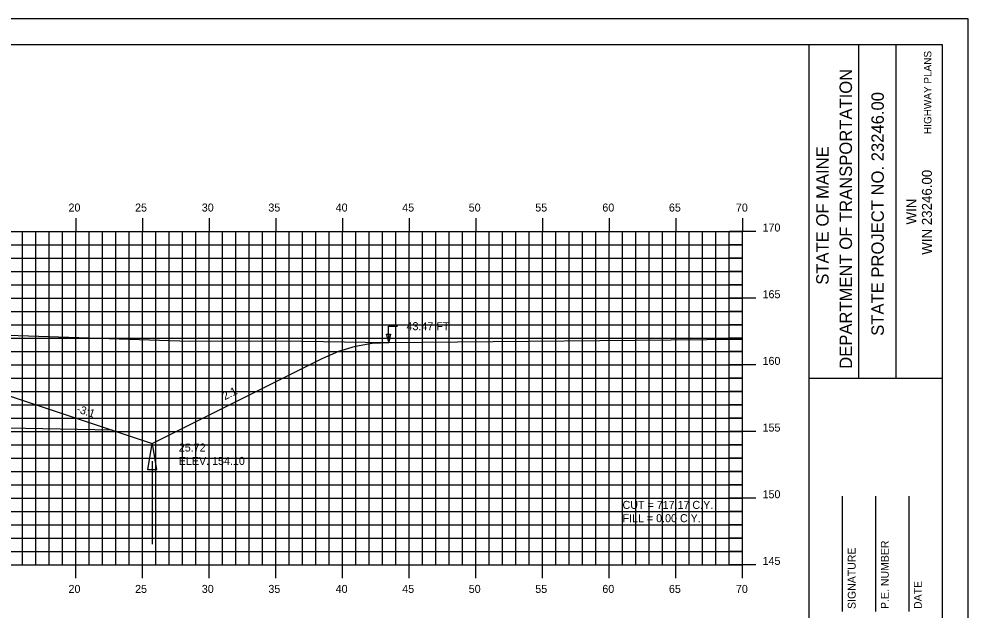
# Model space of a CAD drawing. Extents: x 1143198 to 1143368, y 608981 to 609091.
# Drawn here: x 1143297.1 to 1143368.2, y 609047 to 609091.3 of the extents above; entities that cross this region are included whole.
import ezdxf

# ---------------------------------------------------------------- set-up
doc = ezdxf.new("R2010")
doc.units = 0
for name, color, linetype in [('ANNOTATION', 7, 'Continuous'), ('BORDER', 7, 'Continuous'), ('D_Drainage_Ditch_Line', 7, 'Continuous'), ('D_Roadway_SlopeLines', 7, 'Continuous'), ('D_Roadway_SubGrade', 7, 'Continuous'), ('D_Text_Standard', 7, 'Continuous'), ('H_V ANNOTATION', 7, 'Continuous'), ('HIGHWAY_TITLE', 7, 'Continuous'), ('MAJOR', 7, 'Continuous'), ('MINOR', 7, 'Continuous'), ('PLOT BOUNDARY', 7, 'Continuous'), ('S_Roadway_Centerline', 7, 'Continuous')]:
    doc.layers.add(name, color=color, linetype=linetype)

msp = doc.modelspace()

# ---------------------------------------------------------------- linework, layer by layer
msp.add_lwpolyline([(1143238.561, 609066.856), (1143239.811, 609066.712), (1143241.061, 609066.431), (1143242.311, 609066.013), (1143243.561, 609065.457), (1143255.598, 609059.438), (1143258.598, 609060.438), (1143266.322, 609063.012), (1143266.323, 609063.012), (1143270.323, 609063.172), (1143281.323, 609063.392), (1143292.323, 609063.172), (1143296.323, 609063.012), (1143304.047, 609060.438), (1143307.047, 609059.438), (1143319.789, 609065.809), (1143321.039, 609066.354), (1143322.289, 609066.738), (1143323.539, 609066.962), (1143324.789, 609067.025)])
at = {"layer": 'BORDER'}
for p, q in [((1143356.323, 608984.335), (1143356.323, 609089.335)), ((1143360.052, 609064.332), (1143360.052, 609089.332)), ((1143362.847, 609064.332), (1143362.847, 609089.332)), ((1143356.324, 609064.329), (1143366.323, 609064.329)), ((1143358.823, 609046.838), (1143358.823, 609055.485)), ((1143361.323, 609046.838), (1143361.323, 609055.485)), ((1143363.823, 609046.838), (1143363.823, 609055.485))]:
    msp.add_line(p, q, dxfattribs=at)
msp.add_lwpolyline([(1143206.323, 608984.335), (1143366.323, 608984.335), (1143366.323, 609089.335), (1143206.323, 609089.335)], close=True, dxfattribs=at)
at = {"layer": 'D_Drainage_Ditch_Line'}
msp.add_line((1143307.047, 609058.126), (1143307.046, 609051.882), dxfattribs=at)
msp.add_lwpolyline([(1143307.375, 609057.469), (1143306.718, 609057.469), (1143307.047, 609059.438)], close=True, dxfattribs=at)
at = {"layer": 'D_Roadway_SlopeLines'}
for points in [[(1143307.047, 609059.438), (1143319.789, 609065.809), (1143321.039, 609066.354), (1143322.289, 609066.738), (1143323.539, 609066.962), (1143324.789, 609067.025)], [(1143304.047, 609060.438), (1143307.047, 609059.438)]]:
    msp.add_lwpolyline(points, dxfattribs=at)
at = {"layer": 'D_Roadway_SubGrade'}
msp.add_lwpolyline([(1143292.323, 609062.756), (1143292.323, 609062.922), (1143296.323, 609062.762), (1143296.323, 609063.012), (1143296.323, 609063.012), (1143304.047, 609060.438), (1143292.323, 609060.672)], close=True, dxfattribs=at)
at = {"layer": 'D_Text_Standard'}
msp.add_lwpolyline([(1143324.789, 609067.059), (1143324.632, 609067.638), (1143324.923, 609067.644)], close=True, dxfattribs=at)
msp.add_lwpolyline([(1143324.789, 609067.059), (1143324.765, 609068.237), (1143325.445, 609068.237)], dxfattribs=at)
at = {"layer": 'MAJOR'}
for p, q in [((1143301.323, 609076.337), (1143301.323, 609075.335)), ((1143306.323, 609076.337), (1143306.323, 609075.335)), ((1143311.323, 609076.337), (1143311.323, 609075.335)), ((1143316.323, 609076.337), (1143316.323, 609075.335)), ((1143321.323, 609076.337), (1143321.323, 609075.335)), ((1143326.323, 609076.337), (1143326.323, 609075.335)), ((1143331.323, 609076.337), (1143331.323, 609075.335)), ((1143336.323, 609076.337), (1143336.323, 609075.335)), ((1143341.323, 609076.337), (1143341.323, 609075.335)), ((1143346.323, 609076.337), (1143346.323, 609075.335)), ((1143351.323, 609076.337), (1143351.323, 609075.335)), ((1143211.323, 609075.335), (1143351.323, 609075.335)), ((1143211.323, 609075.335), (1143351.323, 609075.335)), ((1143301.323, 609050.335), (1143301.323, 609075.335)), ((1143306.323, 609050.335), (1143306.323, 609075.335)), ((1143311.323, 609050.335), (1143311.323, 609075.335)), ((1143316.323, 609050.335), (1143316.323, 609075.335)), ((1143321.323, 609050.335), (1143321.323, 609075.335)), ((1143326.323, 609050.335), (1143326.323, 609075.335)), ((1143331.323, 609050.335), (1143331.323, 609075.335)), ((1143336.323, 609050.335), (1143336.323, 609075.335)), ((1143341.323, 609050.335), (1143341.323, 609075.335)), ((1143346.323, 609050.335), (1143346.323, 609075.335)), ((1143352.325, 609075.335), (1143350.321, 609075.335)), ((1143351.323, 609050.335), (1143351.323, 609075.335)), ((1143351.323, 609050.335), (1143351.323, 609075.335)), ((1143211.323, 609070.335), (1143351.323, 609070.335)), ((1143352.325, 609070.335), (1143350.321, 609070.335)), ((1143211.323, 609065.335), (1143351.323, 609065.335)), ((1143352.325, 609065.335), (1143350.321, 609065.335)), ((1143211.323, 609060.335), (1143351.323, 609060.335)), ((1143352.325, 609060.335), (1143350.321, 609060.335)), ((1143211.323, 609055.335), (1143351.323, 609055.335)), ((1143352.325, 609055.335), (1143350.321, 609055.335)), ((1143211.323, 609050.335), (1143351.323, 609050.335)), ((1143211.323, 609050.335), (1143351.323, 609050.335)), ((1143301.323, 609049.333), (1143301.323, 609050.335)), ((1143306.323, 609049.333), (1143306.323, 609050.335)), ((1143311.323, 609049.333), (1143311.323, 609050.335)), ((1143316.323, 609049.333), (1143316.323, 609050.335)), ((1143321.323, 609049.333), (1143321.323, 609050.335)), ((1143326.323, 609049.333), (1143326.323, 609050.335)), ((1143331.323, 609049.333), (1143331.323, 609050.335)), ((1143336.323, 609049.333), (1143336.323, 609050.335)), ((1143341.323, 609049.333), (1143341.323, 609050.335)), ((1143346.323, 609049.333), (1143346.323, 609050.335)), ((1143352.325, 609050.335), (1143350.321, 609050.335)), ((1143351.323, 609049.333), (1143351.323, 609050.335))]:
    msp.add_line(p, q, dxfattribs=at)
at = {"layer": 'MINOR'}
for p, q in [((1143297.323, 609050.335), (1143297.323, 609075.335)), ((1143298.323, 609050.335), (1143298.323, 609075.335)), ((1143299.323, 609050.335), (1143299.323, 609075.335)), ((1143300.323, 609050.335), (1143300.323, 609075.335)), ((1143302.323, 609050.335), (1143302.323, 609075.335)), ((1143303.323, 609050.335), (1143303.323, 609075.335)), ((1143304.323, 609050.335), (1143304.323, 609075.335)), ((1143305.323, 609050.335), (1143305.323, 609075.335)), ((1143307.323, 609050.335), (1143307.323, 609075.335)), ((1143308.323, 609050.335), (1143308.323, 609075.335)), ((1143309.323, 609050.335), (1143309.323, 609075.335)), ((1143310.323, 609050.335), (1143310.323, 609075.335)), ((1143312.323, 609050.335), (1143312.323, 609075.335)), ((1143313.323, 609050.335), (1143313.323, 609075.335)), ((1143314.323, 609050.335), (1143314.323, 609075.335)), ((1143315.323, 609050.335), (1143315.323, 609075.335)), ((1143317.323, 609050.335), (1143317.323, 609075.335)), ((1143318.323, 609050.335), (1143318.323, 609075.335)), ((1143319.323, 609050.335), (1143319.323, 609075.335)), ((1143320.323, 609050.335), (1143320.323, 609075.335)), ((1143322.323, 609050.335), (1143322.323, 609075.335)), ((1143323.323, 609050.335), (1143323.323, 609075.335)), ((1143324.323, 609050.335), (1143324.323, 609075.335)), ((1143325.323, 609050.335), (1143325.323, 609075.335)), ((1143327.323, 609050.335), (1143327.323, 609075.335)), ((1143328.323, 609050.335), (1143328.323, 609075.335)), ((1143329.323, 609050.335), (1143329.323, 609075.335)), ((1143330.323, 609050.335), (1143330.323, 609075.335)), ((1143332.323, 609050.335), (1143332.323, 609075.335)), ((1143333.323, 609050.335), (1143333.323, 609075.335)), ((1143334.323, 609050.335), (1143334.323, 609075.335)), ((1143335.323, 609050.335), (1143335.323, 609075.335)), ((1143337.323, 609050.335), (1143337.323, 609075.335)), ((1143338.323, 609050.335), (1143338.323, 609075.335)), ((1143339.323, 609050.335), (1143339.323, 609075.335)), ((1143340.323, 609050.335), (1143340.323, 609075.335)), ((1143342.323, 609050.335), (1143342.323, 609075.335)), ((1143343.323, 609050.335), (1143343.323, 609075.335)), ((1143344.323, 609050.335), (1143344.323, 609075.335)), ((1143345.323, 609050.335), (1143345.323, 609075.335)), ((1143347.323, 609050.335), (1143347.323, 609075.335)), ((1143348.323, 609050.335), (1143348.323, 609075.335)), ((1143349.323, 609050.335), (1143349.323, 609075.335)), ((1143350.323, 609050.335), (1143350.323, 609075.335)), ((1143211.323, 609074.335), (1143351.323, 609074.335)), ((1143351.323, 609074.335), (1143350.321, 609074.335)), ((1143211.323, 609073.335), (1143351.323, 609073.335)), ((1143351.323, 609073.335), (1143350.321, 609073.335)), ((1143211.323, 609072.335), (1143351.323, 609072.335)), ((1143351.323, 609072.335), (1143350.321, 609072.335)), ((1143211.323, 609071.335), (1143351.323, 609071.335)), ((1143351.323, 609071.335), (1143350.321, 609071.335)), ((1143211.323, 609069.335), (1143351.323, 609069.335)), ((1143351.323, 609069.335), (1143350.321, 609069.335)), ((1143211.323, 609068.335), (1143351.323, 609068.335)), ((1143351.323, 609068.335), (1143350.321, 609068.335)), ((1143211.323, 609067.335), (1143351.323, 609067.335)), ((1143351.323, 609067.335), (1143350.321, 609067.335)), ((1143211.323, 609066.335), (1143351.323, 609066.335)), ((1143351.323, 609066.335), (1143350.321, 609066.335)), ((1143211.323, 609064.335), (1143351.323, 609064.335)), ((1143351.323, 609064.335), (1143350.321, 609064.335)), ((1143211.323, 609063.335), (1143351.323, 609063.335)), ((1143351.323, 609063.335), (1143350.321, 609063.335)), ((1143211.323, 609062.335), (1143351.323, 609062.335)), ((1143351.323, 609062.335), (1143350.321, 609062.335)), ((1143211.323, 609061.335), (1143351.323, 609061.335)), ((1143351.323, 609061.335), (1143350.321, 609061.335)), ((1143211.323, 609059.335), (1143351.323, 609059.335)), ((1143351.323, 609059.335), (1143350.321, 609059.335)), ((1143211.323, 609058.335), (1143351.323, 609058.335)), ((1143351.323, 609058.335), (1143350.321, 609058.335)), ((1143211.323, 609057.335), (1143351.323, 609057.335)), ((1143351.323, 609057.335), (1143350.321, 609057.335)), ((1143211.323, 609056.335), (1143351.323, 609056.335)), ((1143351.323, 609056.335), (1143350.321, 609056.335)), ((1143211.323, 609054.335), (1143351.323, 609054.335)), ((1143351.323, 609054.335), (1143350.321, 609054.335)), ((1143211.323, 609053.335), (1143351.323, 609053.335)), ((1143351.323, 609053.335), (1143350.321, 609053.335)), ((1143211.323, 609052.335), (1143351.323, 609052.335)), ((1143351.323, 609052.335), (1143350.321, 609052.335)), ((1143211.323, 609051.335), (1143351.323, 609051.335)), ((1143351.323, 609051.335), (1143350.321, 609051.335))]:
    msp.add_line(p, q, dxfattribs=at)
at = {"layer": 'PLOT BOUNDARY'}
msp.add_lwpolyline([(1143198.23, 608981.276), (1143368.23, 608981.276), (1143368.23, 609091.276), (1143198.23, 609091.276)], close=True, dxfattribs=at)
at = {"layer": 'S_Roadway_Centerline'}
msp.add_lwpolyline([(1143290.923, 609067.734), (1143309.881, 609067.108), (1143316.777, 609067.145), (1143324.592, 609067.023), (1143351.323, 609067.262)], dxfattribs=at)

# ---------------------------------------------------------------- texts
at = {"layer": 'ANNOTATION'}
for s, rotation, p in [('2:1', 26.56505, (1143312.49, 609062.678)), ('-3:1', 341.56521, (1143301.334, 609061.796))]:
    msp.add_text(s, height=0.6, rotation=rotation, dxfattribs=at).set_placement(p)
at = {"layer": 'BORDER'}
for s, height, p in [('DEPARTMENT OF TRANSPORTATION', 0.93176, (1143359.53, 609065.041)), ('STATE PROJECT NO. 23246.00', 0.93176, (1143361.915, 609067.517)), ('STATE OF MAINE', 0.93176, (1143357.779, 609071.347)), ('WIN 23246.00', 0.74527, (1143365.519, 609073.596)), ('WIN', 0.7453, (1143364.36, 609075.865)), ('P.E. NUMBER', 0.59055, (1143362.284, 609047.03)), ('SIGNATURE', 0.5906, (1143359.804, 609047.03)), ('DATE', 0.5906, (1143364.764, 609047.03))]:
    msp.add_text(s, height=height, rotation=90, dxfattribs=at).set_placement(p)
at = {"layer": 'D_Text_Standard'}
for s, p in [('43.47 FT', (1143326.125, 609067.937)), ('25.72', (1143309.047, 609058.838)), ('ELEV. 154.10', (1143309.047, 609057.836)), ('CUT = 717.17 C.Y.', (1143342.323, 609054.535)), ('FILL = 0.00 C.Y.', (1143342.323, 609053.539))]:
    msp.add_text(s, height=0.6, dxfattribs=at).set_placement(p)
at = {"layer": 'H_V ANNOTATION'}
for s, p in [('20', (1143300.777, 609076.835)), ('25', (1143305.769, 609076.835)), ('30', (1143310.772, 609076.835)), ('35', (1143315.764, 609076.835)), ('40', (1143320.809, 609076.835)), ('45', (1143325.801, 609076.835)), ('50', (1143330.788, 609076.835)), ('55', (1143335.78, 609076.835)), ('60', (1143340.809, 609076.835)), ('65', (1143345.801, 609076.835)), ('70', (1143350.825, 609076.835)), ('170', (1143352.823, 609075.335)), ('165', (1143352.823, 609070.335)), ('160', (1143352.823, 609065.335)), ('155', (1143352.823, 609060.335)), ('150', (1143352.823, 609055.335)), ('145', (1143352.823, 609050.335)), ('20', (1143300.777, 609048.235)), ('25', (1143305.769, 609048.235)), ('30', (1143310.772, 609048.235)), ('35', (1143315.764, 609048.235)), ('40', (1143320.809, 609048.235)), ('45', (1143325.801, 609048.235)), ('50', (1143330.788, 609048.235)), ('55', (1143335.78, 609048.235)), ('60', (1143340.809, 609048.235)), ('65', (1143345.801, 609048.235)), ('70', (1143350.825, 609048.235))]:
    msp.add_text(s, height=0.6, dxfattribs=at).set_placement(p)
at = {"layer": 'HIGHWAY_TITLE'}
msp.add_text('HIGHWAY PLANS', height=0.55901, rotation=90, dxfattribs=at).set_placement((1143365.482, 609082.65))

doc.saveas('drawing.dxf')
